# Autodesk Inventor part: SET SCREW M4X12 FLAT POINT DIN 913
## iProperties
IsCustomPart: 1
Created: 2006-02
Part Number: SET SCREW M4X12 FLAT POINT DIN 913
Material: Steel, Mild
Description: Hexagon Socket Set Screw
Document SubType Name: Modeling
Standard: DIN 913
Designer: Andy Moles
Standards Organization: DIN
Language: en-US
Size Designation: M4 x 12
Categories: <MemberInstance><Categories><Category DisplayName="Fasteners" InternalName="e4da775c-781d-43d5-af7c-5136215cf5a6" Mnemonic="FSTN"><Category DisplayName="Bolts"
Density: 1 g/cm^3
Author: Andy Moles
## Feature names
1. Body [Revolution]
2. Slot [Extrusion]
3. Chamfer1
4. Chamfer2
